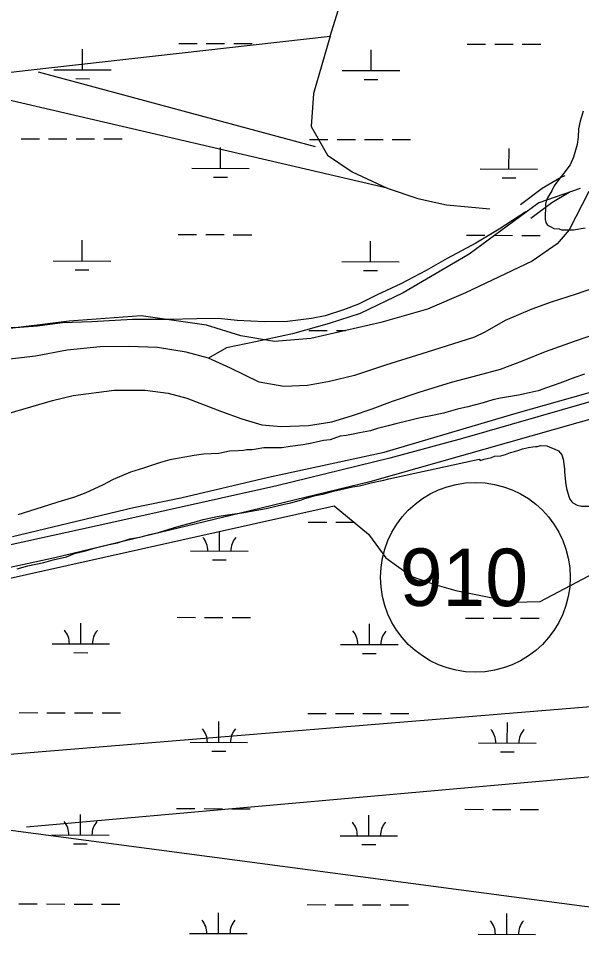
# Model space of a CAD drawing. Extents: x 3172297 to 3210190, y 958463 to 983887.
# Drawn here: x 3185925 to 3186905, y 976980 to 978578 of the extents above; entities that cross this region are included whole.
import ezdxf

# ---------------------------------------------------------------- set-up
doc = ezdxf.new("R2010")
doc.units = 0
for name, color, linetype in [('V-ROAD-CNTR', 7, 'Continuous'), ('V-ROAD-IDEN', 7, 'Continuous'), ('V-SITE-VEGE', 7, 'Continuous'), ('V-TOPO-SHOR', 7, 'Continuous'), ('V-WETL-SWMP', 7, 'Continuous')]:
    doc.layers.add(name, color=color, linetype=linetype)

msp = doc.modelspace()

# ---------------------------------------------------------------- linework, layer by layer
at = {"layer": 'V-ROAD-CNTR'}
for points in [[(3186875.9, 978303.9), (3186870.3, 978301.5), (3186836.5, 978281.5), (3186798.9, 978253.2)], [(3186884.4, 978274.9), (3186883.8, 978274.7), (3186853.2, 978256.5), (3186816.9, 978229.2)], [(3186807.9, 978241.2), (3186761.6, 978210.9), (3186721.1, 978186.7), (3186671.5, 978159.9), (3186634.5, 978138.8), (3186590.5, 978115.7), (3186549.7, 978096.9), (3186516.8, 978080.2), (3186491, 978070.9), (3186458.9, 978060.1), (3186435.3, 978055.8), (3186393.5, 978050.2), (3186353.2, 978050), (3186306.1, 978051.8), (3186273.1, 978055.7), (3186235.7, 978055.1), (3186186.4, 978053.9), (3186123.7, 978054), (3186053.1, 978049.6), (3186001.9, 978048.1), (3185958.4, 978042), (3185928, 978040.1)], [(3187601.4, 978101.2), (3187581.5, 978096.2), (3187447.5, 978057.8), (3187093.6, 977958.8), (3186913.9, 977908.7), (3186698.1, 977847.1), (3186571.4, 977812.9), (3186374.8, 977764.7), (3186086.1, 977700), (3185607.3, 977595.4), (3185266, 977517.5), (3185104.6, 977484.2), (3185035.5, 977468.1), (3184958.9, 977461.2), (3184851, 977449.3), (3184588.3, 977432.2), (3184367.5, 977423.5)], [(3185928, 978040.1), (3185691.8, 978032.1), (3185529.4, 977981.2), (3185207, 977853.7), (3184853.5, 977722.8)]]:
    msp.add_lwpolyline(points, dxfattribs=at)
at = {"layer": 'V-ROAD-IDEN'}
msp.add_circle((3186720.3, 977605.4), 165, dxfattribs=at)
msp.add_circle((3186720.3, 977605.4), 165, dxfattribs=at)
at = {"layer": 'V-SITE-VEGE'}
for p, q in [((3186908, 978416.4), (3186902.4, 978398.5)), ((3186902.4, 978398.5), (3186900, 978385.3)), ((3186900, 978385.3), (3186899.1, 978371.2)), ((3186899.1, 978371.2), (3186897.5, 978358)), ((3186897.5, 978358), (3186891.1, 978336.1)), ((3186891.1, 978336.1), (3186885.5, 978322.9)), ((3186885.5, 978322.9), (3186874.5, 978308.1)), ((3186867.4, 978299.6), (3186857.2, 978286.4)), ((3186874.5, 978308.1), (3186867.4, 978299.6)), ((3186857.2, 978286.4), (3186853.2, 978277.8)), ((3186853.2, 978277.8), (3186846.1, 978265.4)), ((3186842.1, 978254.5), (3186841.9, 978227.9)), ((3186843.7, 978259.9), (3186842.1, 978254.5)), ((3186846.1, 978265.4), (3186843.7, 978259.9)), ((3186841.9, 978227.9), (3186842.7, 978222.5)), ((3186842.7, 978222.5), (3186845.8, 978217.8)), ((3186845.8, 978217.8), (3186848.1, 978217)), ((3186848.1, 978217), (3186852.8, 978214.6)), ((3186852.8, 978214.6), (3186856.7, 978212.2)), ((3186856.7, 978212.2), (3186866, 978211.4)), ((3186866, 978211.4), (3186869.9, 978209.8)), ((3186869.9, 978209.8), (3186891, 978209.7)), ((3186891, 978209.7), (3186911.3, 978213.4)), ((3186893.2, 977952.8), (3186867.4, 977942.8)), ((3186910.4, 977958.9), (3186893.2, 977952.8)), ((3186843.9, 977935.1), (3186829.8, 977929.8)), ((3186867.4, 977942.8), (3186843.9, 977935.1)), ((3186764.2, 977916.9), (3186750.9, 977913.9)), ((3186795.4, 977922.2), (3186764.2, 977916.9)), ((3186814.2, 977926), (3186795.4, 977922.2)), ((3186829.8, 977929.8), (3186814.2, 977926)), ((3186707.1, 977901.7), (3186689.1, 977897.9)), ((3186733.7, 977908.6), (3186707.1, 977901.7)), ((3186750.9, 977913.9), (3186733.7, 977908.6)), ((3186648.4, 977887.3), (3186621.8, 977882)), ((3186664.8, 977891.1), (3186648.4, 977887.3)), ((3186689.1, 977897.9), (3186664.8, 977891.1)), ((3186568.7, 977869), (3186549.9, 977864.5)), ((3186581.9, 977872.1), (3186568.7, 977869)), ((3186603.1, 977877.4), (3186581.9, 977872.1)), ((3186621.8, 977882), (3186603.1, 977877.4)), ((3186485, 977850.9), (3186467.8, 977844.7)), ((3186495.9, 977852.3), (3186485, 977850.9)), ((3186507.7, 977854.6), (3186495.9, 977852.3)), ((3186518.6, 977856.9), (3186507.7, 977854.6)), ((3186538.1, 977859.9), (3186518.6, 977856.9)), ((3186549.9, 977864.5), (3186538.1, 977859.9)), ((3186420.9, 977835.7), (3186398.2, 977832.7)), ((3186435.7, 977838.7), (3186420.9, 977835.7)), ((3186456.1, 977843.2), (3186435.7, 977838.7)), ((3186467.8, 977844.7), (3186456.1, 977843.2)), ((3186247.4, 977819.6), (3186231, 977817.4)), ((3186274, 977821), (3186247.4, 977819.6)), ((3186292.8, 977824.8), (3186274, 977821)), ((3186307.6, 977825.5), (3186292.8, 977824.8)), ((3186317, 977826.2), (3186307.6, 977825.5)), ((3186322.4, 977827), (3186317, 977826.2)), ((3186331.8, 977826.9), (3186322.4, 977827)), ((3186338.8, 977828.4), (3186331.8, 977826.9)), ((3186352.1, 977830.7), (3186338.8, 977828.4)), ((3186383.4, 977830.5), (3186352.1, 977830.7)), ((3186398.2, 977832.7), (3186383.4, 977830.5)), ((3186172.4, 977805.3), (3186142.7, 977795.3)), ((3186188.8, 977809.9), (3186172.4, 977805.3)), ((3186214.6, 977814.4), (3186188.8, 977809.9)), ((3186231, 977817.4), (3186214.6, 977814.4)), ((3186120, 977788.5), (3186090.2, 977775.4)), ((3186142.7, 977795.3), (3186120, 977788.5)), ((3186090.2, 977775.4), (3186071.4, 977765.4)), ((3186071.4, 977765.4), (3186042.4, 977752.3)), ((3186022.9, 977744.6), (3185993.9, 977736.2)), ((3186042.4, 977752.3), (3186022.9, 977744.6)), ((3185977.5, 977730.9), (3185924.3, 977714)), ((3185993.9, 977736.2), (3185977.5, 977730.9))]:
    msp.add_line(p, q, dxfattribs=at)
msp.add_lwpolyline([(3185923, 977619.9), (3185941.8, 977625.3), (3185969.2, 977631.3), (3185985.6, 977635.9), (3186009, 977641.2), (3186023.1, 977646.6), (3186044.2, 977651.9), (3186059.1, 977656.5), (3186083.3, 977662.6), (3186097.4, 977665.6), (3186119.3, 977672.5), (3186136.5, 977675.5), (3186153.7, 977680.1), (3186170.9, 977683.9), (3186195.2, 977691.5), (3186209.3, 977695.3), (3186231.2, 977701.4), (3186246.8, 977706), (3186271, 977711.3), (3186289, 977714.3), (3186314, 977717.3), (3186356.2, 977724.8), (3186387.5, 977732.4), (3186399.2, 977734.7), (3186418, 977740), (3186423.5, 977742.3), (3186442.3, 977747.7), (3186454.8, 977749.9), (3186473.5, 977755.3), (3186486.1, 977758.3), (3186506.4, 977762.9), (3186518.9, 977764.3), (3186536.9, 977768.9), (3186546.3, 977771.2), (3186561.1, 977774.2), (3186569.7, 977776.5), (3186727.2, 977810.9), (3186728.8, 977808.5), (3186735.8, 977810.8), (3186748.3, 977813.9), (3186753.8, 977816.2), (3186764.7, 977816.9), (3186772.6, 977819.2), (3186781.2, 977822.2), (3186788.2, 977824.5), (3186796, 977826.8), (3186802.3, 977829.1), (3186812.5, 977831.4), (3186820.3, 977832.1), (3186825, 977832.9), (3186828.1, 977832.8), (3186833.6, 977834.4), (3186844.5, 977834.3), (3186849.9, 977831.9), (3186857.7, 977828.7), (3186864.7, 977825.6), (3186870.9, 977818.5), (3186873.2, 977810.7), (3186875.5, 977794.3), (3186875.4, 977788.8), (3186876.9, 977770.8), (3186879.1, 977759.9), (3186883, 977745.8), (3186884.5, 977741.1), (3186888.4, 977736.4), (3186889.9, 977734.8), (3186897.7, 977730.9), (3186904.7, 977729.3), (3186946.9, 977729)], dxfattribs=at)
at = {"layer": 'V-TOPO-SHOR'}
for p, q in [((3186442, 978353.9), (3185960.2, 978483.7)), ((3186566.8, 978282.2), (3185760.2, 978469.9)), ((3185346.5, 977251.4), (3187118.1, 977397)), ((3185939.1, 977171.4), (3187110.6, 977275.6))]:
    msp.add_line(p, q, dxfattribs=at)
for points in [[(3184872.8, 977754.3), (3184833.5, 977768.7), (3184819.3, 977786.6), (3184805.2, 977854.4), (3184820.7, 978357.9), (3185942.3, 978487.3), (3186467.4, 978546.7), (3186607.8, 978996.3), (3186679.5, 979099.7)], [(3186467.4, 978546.7), (3186438.6, 978446.8), (3186434.9, 978389.6), (3186463.3, 978339.6), (3186506.1, 978310.9), (3186566.8, 978282.2), (3186620.3, 978264.2), (3186670.3, 978253.4), (3186745.2, 978246)], [(3186937.2, 977884.9), (3186536.9, 977771.6), (3186311.8, 977716.8), (3185988.4, 977639), (3185758, 977589.6), (3185561.5, 977547.2), (3185359.6, 977494.2), (3185150.6, 977444.7), (3185014.8, 977420), (3184898.7, 977411.4), (3184845.1, 977409.7), (3184334.4, 977387.8), (3183970.1, 977360.1), (3183875.5, 977353.2), (3183841.6, 977358.7), (3183725.6, 977405.4), (3183540.1, 977488), (3183179.8, 977637.1), (3183062.1, 977696.3), (3183005.1, 977737.5), (3182491.6, 978020.9), (3182019, 978279.1)], [(3186902.4, 978281.4), (3186831, 978256.5), (3186709.3, 978167.6), (3186594.9, 978100), (3186519.8, 978064.5), (3186466.2, 978046.7), (3186401.9, 978029), (3186337.6, 978014.9), (3186287.5, 978004.3), (3186256.1, 977986.7)], [(3185914.9, 977676.3), (3186125.7, 977726.6), (3186207.9, 977743.4), (3186360.6, 977779.6), (3186561.6, 977822.9), (3186791.2, 977891), (3187064.6, 977968), (3187199.5, 978004.3), (3187440.7, 978071.6), (3187492.5, 978092), (3187508.6, 978100.9), (3187520.3, 978109.8), (3187525.6, 978116), (3187512.4, 978196.4), (3187504.6, 978258.9)], [(3186941.1, 978113.8), (3186895.9, 978098.1), (3186852.1, 978084.2), (3186818.4, 978071.6), (3186772, 978051.9), (3186736.5, 978031.9), (3186718.8, 978023.3), (3186680.8, 978011.1), (3186627.3, 977994.1), (3186564.2, 977974.1), (3186509.9, 977956.6), (3186466.7, 977945.8), (3186428.5, 977939.2), (3186387.1, 977937.5), (3186344, 977944.8), (3186294.1, 977969.2), (3186256.1, 977986.7), (3186217.1, 977997.1), (3186167, 978005), (3186116.9, 978006.8), (3186067.5, 978006), (3186010.1, 978000.6), (3185954.8, 977990.1)], [(3185984.8, 977912.9), (3186020.4, 977921.9), (3186092.1, 977930.8), (3186145.9, 977930.7), (3186185.7, 977925.4), (3186218.5, 977917.2), (3186278.6, 977893.7), (3186313.9, 977881.2), (3186348.6, 977870.7), (3186382.6, 977867.8), (3186429.8, 977869.4), (3186470.5, 977876), (3186506.7, 977886.8), (3186541, 977898.3), (3186576.4, 977911.5), (3186622.6, 977927.3), (3186678.7, 977945), (3186725.2, 977957.2), (3186763.9, 977967.6), (3186802.1, 977981.7), (3186842.2, 977998.2), (3186893, 978016), (3186936.7, 978031)], [(3185954.8, 977990.1), (3185720.5, 977962.9), (3185538.3, 977931.2), (3185377.5, 977874.5), (3185291.7, 977842.5), (3185241.6, 977799.8), (3185184.4, 977760.7), (3185152.2, 977732.2), (3185134.3, 977725.1), (3185091.4, 977707.3), (3185084.2, 977700.2), (3185080.6, 977671.6), (3185091.2, 977635.9), (3185098.3, 977614.5), (3185112.5, 977585.9), (3185144.7, 977589.3), (3185187.6, 977610.7), (3185252, 977653.4), (3185309.2, 977692.5), (3185366.4, 977735.2), (3185430.8, 977774.3), (3185555.9, 977799), (3185702.3, 977830.8), (3185984.8, 977912.9)], [(3184511.2, 977389.1), (3184625.3, 977331.7), (3185867.7, 977171.5), (3186910.1, 977033.3), (3187131.4, 977011.3)]]:
    msp.add_lwpolyline(points, dxfattribs=at)
at = {"layer": 'V-WETL-SWMP'}
for p, q in [((3186036.9, 978488.1), (3186037, 978524.1)), ((3186204.1, 978534.1), (3186236.1, 978534)), ((3186252.1, 978533.9), (3186284.1, 978533.9)), ((3186300.1, 978533.8), (3186332.1, 978533.7)), ((3186538.8, 978486.8), (3186538.9, 978522.8)), ((3186706, 978532.8), (3186738, 978532.7)), ((3186754, 978532.7), (3186786, 978532.6)), ((3186802, 978532.6), (3186834, 978532.5)), ((3185986.9, 978488.2), (3186086.9, 978488)), ((3186488.8, 978487), (3186588.8, 978486.7)), ((3186024.9, 978472.7), (3186048.9, 978472.6)), ((3186526.8, 978471.4), (3186550.8, 978471.4)), ((3185929.8, 978368.3), (3185961.8, 978368.3)), ((3185977.8, 978368.2), (3186009.7, 978368.1)), ((3186025.7, 978368.1), (3186057.7, 978368)), ((3186073.7, 978368), (3186105.7, 978367.9)), ((3186431.6, 978367.1), (3186463.6, 978367)), ((3186479.6, 978367), (3186511.6, 978366.9)), ((3186527.6, 978366.9), (3186559.6, 978366.8)), ((3186575.6, 978366.7), (3186607.6, 978366.7)), ((3186276.9, 978316.8), (3186277, 978352.7)), ((3186778.8, 978315.5), (3186778.9, 978351.5)), ((3186226.9, 978316.9), (3186326.9, 978316.6)), ((3186728.8, 978315.6), (3186828.7, 978315.4)), ((3186264.8, 978301.4), (3186288.8, 978301.3)), ((3186766.7, 978300.1), (3186790.7, 978300.1)), ((3186917.5, 978276.5), (3186883.4, 978209.8)), ((3186883.4, 978209.8), (3186862.6, 978185.4)), ((3186036, 978155.6), (3186036.1, 978191.6)), ((3186203.2, 978201.6), (3186235.1, 978201.5)), ((3186251.1, 978201.5), (3186283.1, 978201.4)), ((3186299.1, 978201.3), (3186331.1, 978201.3)), ((3186537.8, 978154.3), (3186537.9, 978190.3)), ((3186705, 978200.3), (3186737, 978200.3)), ((3186753, 978200.2), (3186785, 978200.1)), ((3186801, 978200.1), (3186833, 978200)), ((3186862.6, 978185.4), (3186819.2, 978155.2)), ((3185986, 978155.7), (3186086, 978155.5)), ((3186487.8, 978154.5), (3186587.8, 978154.2)), ((3186819.2, 978155.2), (3186703.4, 978100.1)), ((3186023.9, 978140.2), (3186047.9, 978140.1)), ((3186525.8, 978139), (3186549.8, 978138.9)), ((3186703.4, 978100.1), (3186637.1, 978071.9)), ((3186138.7, 978060.4), (3186013.4, 978050.9)), ((3186252.4, 978043.9), (3186138.7, 978060.4)), ((3186637.1, 978071.9), (3186555.6, 978048.7)), ((3186013.4, 978050.9), (3185892, 978035.9)), ((3186312.5, 978025.3), (3186252.4, 978043.9)), ((3186555.6, 978048.7), (3186434.1, 978020.6)), ((3186430.6, 978034.6), (3186462.6, 978034.5)), ((3186478.6, 978034.5), (3186494.2, 978034.5)), ((3186371.1, 978015.4), (3186312.5, 978025.3)), ((3186434.1, 978020.6), (3186371.1, 978015.4)), ((3186429.6, 977701.4), (3186461.6, 977701.3)), ((3186477.6, 977701.3), (3186509.5, 977701.2)), ((3186274.9, 977651.1), (3186274.9, 977685.1)), ((3186224.9, 977651.2), (3186324.9, 977650.9)), ((3186262.8, 977635.6), (3186286.8, 977635.6)), ((3186201.2, 977535.8), (3186233.2, 977535.7)), ((3186249.2, 977535.7), (3186281.2, 977535.6)), ((3186297.2, 977535.6), (3186329.2, 977535.5)), ((3186703.1, 977534.6), (3186735.1, 977534.5)), ((3186751.1, 977534.4), (3186783.1, 977534.4)), ((3186799.1, 977534.3), (3186831.1, 977534.2)), ((3186034, 977489.8), (3186034.1, 977525.8)), ((3186535.9, 977488.5), (3186536, 977524.5)), ((3185984, 977489.9), (3186084, 977489.7)), ((3186485.9, 977488.7), (3186585.9, 977488.4)), ((3186021.9, 977474.4), (3186045.9, 977474.3)), ((3186523.9, 977473.1), (3186547.9, 977473.1)), ((3185926.8, 977370), (3185958.8, 977369.9)), ((3185974.8, 977369.9), (3186006.8, 977369.8)), ((3186022.8, 977369.7), (3186054.8, 977369.7)), ((3186070.8, 977369.6), (3186102.8, 977369.5)), ((3186428.8, 977368.7), (3186460.8, 977368.7)), ((3186476.8, 977368.6), (3186508.8, 977368.5)), ((3186524.8, 977368.5), (3186556.8, 977368.4)), ((3186572.8, 977368.4), (3186604.8, 977368.3)), ((3186274, 977318.4), (3186274.1, 977354.4)), ((3186775.9, 977317.1), (3186776, 977353.1)), ((3186224, 977318.5), (3186324, 977318.3)), ((3186725.9, 977317.3), (3186825.9, 977317)), ((3186262, 977303), (3186286, 977302.9)), ((3186763.9, 977301.7), (3186787.9, 977301.7)), ((3186200.3, 977203.1), (3186232.3, 977203)), ((3186248.3, 977203), (3186280.3, 977202.9)), ((3186296.3, 977202.9), (3186328.3, 977202.8)), ((3186702.2, 977201.9), (3186734.2, 977201.8)), ((3186750.2, 977201.8), (3186782.2, 977201.7)), ((3186798.2, 977201.6), (3186830.2, 977201.6)), ((3186033.2, 977157.1), (3186033.3, 977193.1)), ((3186535.1, 977155.9), (3186535.2, 977191.9)), ((3185983.2, 977157.2), (3186083.2, 977157)), ((3186485.1, 977156), (3186585.1, 977155.7)), ((3186021.1, 977141.7), (3186045.1, 977141.6)), ((3186523, 977140.5), (3186547, 977140.4)), ((3185926, 977037.3), (3185958, 977037.2)), ((3185974, 977037.2), (3186006, 977037.1)), ((3186022, 977037.1), (3186054, 977037)), ((3186070, 977036.9), (3186102, 977036.9)), ((3186273.2, 976985.7), (3186273.3, 977021.7)), ((3186427.9, 977036.1), (3186459.9, 977036)), ((3186475.9, 977035.9), (3186507.9, 977035.9)), ((3186523.9, 977035.8), (3186555.9, 977035.7)), ((3186571.9, 977035.7), (3186603.9, 977035.6)), ((3186775.1, 976984.5), (3186775.2, 977020.5)), ((3186223.2, 976985.8), (3186323.2, 976985.6)), ((3186725.1, 976984.6), (3186825.1, 976984.3))]:
    msp.add_line(p, q, dxfattribs=at)
msp.add_lwpolyline([(3183420.7, 976971.8), (3183413.8, 977038.7), (3183442.4, 977156.4), (3183570.2, 977299.4), (3183714.5, 977305.2), (3184995.4, 977395.2), (3185873.8, 977595.5), (3186474.8, 977729.8), (3186534.4, 977680.7), (3186564.5, 977639), (3186610, 977606.8), (3186650, 977592.6), (3186686.1, 977582.5), (3186788.1, 977562.2), (3186833.1, 977563.1), (3186928.9, 977613.6), (3186981.8, 977670.5), (3187020.2, 977670.9), (3187051.5, 977626.5), (3187060.5, 977559.5), (3187053.9, 977478.4), (3187050.5, 976763)], dxfattribs=at)
for centre, start, end in [((3186219.6, 977651.7), 359.0865, 40.6302), ((3186330.1, 977651.4), 139.0865, 180.6302), ((3185978.7, 977490.4), 359.0865, 40.6302), ((3186089.2, 977490.1), 139.0865, 180.6302), ((3186480.6, 977489.2), 359.0865, 40.6302), ((3186591.1, 977488.9), 139.0865, 180.6302), ((3186218.8, 977319), 359.0865, 40.6302), ((3186329.3, 977318.7), 139.0865, 180.6302), ((3186720.7, 977317.7), 359.0865, 40.6302), ((3186831.2, 977317.5), 139.0865, 180.6302), ((3185977.9, 977157.7), 359.0865, 40.6302), ((3186088.4, 977157.4), 139.0865, 180.6302), ((3186479.8, 977156.5), 359.0865, 40.6302), ((3186590.3, 977156.2), 139.0865, 180.6302), ((3186218, 976986.3), 359.0865, 40.6302), ((3186328.5, 976986), 139.0865, 180.6302), ((3186719.9, 976985.1), 359.0865, 40.6302), ((3186830.4, 976984.8), 139.0865, 180.6302)]:
    msp.add_arc(centre, 35.2, start, end, dxfattribs=at)

# ---------------------------------------------------------------- texts
at = {"layer": 'V-ROAD-IDEN'}
msp.add_text('910', height=100, rotation=359.8583, dxfattribs=at).set_placement((3186588.7, 977555.7))

doc.saveas('drawing.dxf')
